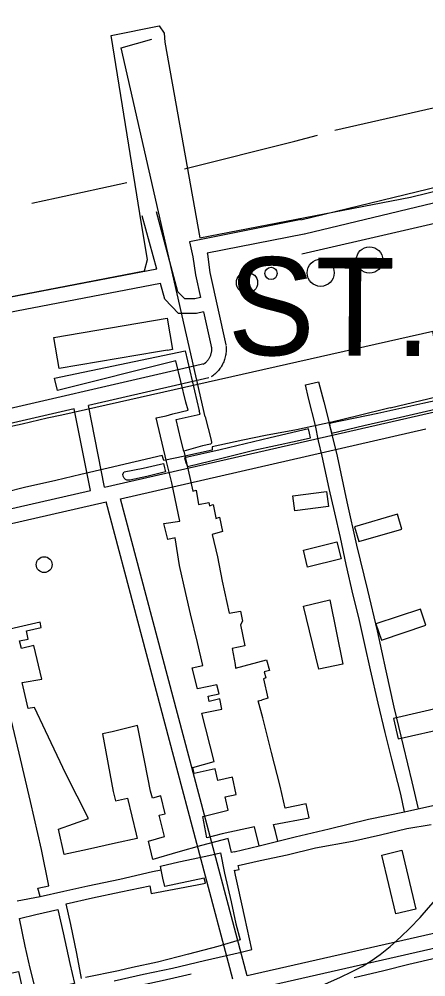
# Model space of a CAD drawing. Extents: x 3392644 to 3430565, y 576657 to 602123.
# Drawn here: x 3418875 to 3419706, y 584989 to 586945 of the extents above; entities that cross this region are included whole.
import ezdxf

# ---------------------------------------------------------------- set-up
doc = ezdxf.new("R2010")
doc.units = 0
for name, color, linetype in [('V-BLDG-OTLN', 7, 'Continuous'), ('V-DOMW-TANK', 7, 'Continuous'), ('V-RAIL-TRAK', 7, 'Continuous'), ('V-ROAD-CNTR', 7, 'Continuous'), ('V-SITE-OTLN', 7, 'Continuous'), ('V-TOPO-GNAM-IDEN', 7, 'Continuous'), ('V-TOPO-SHOR', 7, 'Continuous'), ('V-UTIL-LINE', 7, 'Continuous')]:
    doc.layers.add(name, color=color, linetype=linetype)

msp = doc.modelspace()

# ---------------------------------------------------------------- linework, layer by layer
at = {"layer": 'V-BLDG-OTLN'}
for points in [[(3419158, 586265.5), (3418957, 586231.4), (3418946.2, 586295.1), (3419178, 586334.4), (3419188.8, 586270.5), (3419178.2, 586268.7), (3419178.2, 586268.9)], [(3419434.6, 585971.9), (3419503.5, 585980.8), (3419507.5, 585949.9), (3419438.6, 585941)], [(3419648.7, 585934.1), (3419560.8, 585908.6), (3419569.6, 585878.2), (3419657.6, 585903.7)], [(3419456.2, 585860.9), (3419524.6, 585877.9), (3419533.3, 585843.1), (3419464.9, 585826.1)], [(3419456.3, 585746.5), (3419510.1, 585759.3), (3419537.1, 585628), (3419487.4, 585617.5)], [(3419695.3, 585740.6), (3419604.3, 585710.2), (3419615.5, 585676.9), (3419706.4, 585707.3)], [(3419743.5, 585540.6), (3419640.2, 585517.3), (3419649.6, 585475.6), (3419753, 585498.9)], [(3419616.5, 585238.1), (3419657.5, 585247.8), (3419686, 585127.8), (3419645.3, 585118.2)]]:
    msp.add_lwpolyline(points, close=True, dxfattribs=at)
at = {"layer": 'V-DOMW-TANK'}
for centre, radius in [((3419591.4, 586453.3), 27), ((3419491.4, 586427.2), 27.7), ((3419340.9, 586406.8), 21.6), ((3419390, 586426), 12.5), ((3418926.3, 585831.2), 16.2)]:
    msp.add_circle(centre, radius, dxfattribs=at)
at = {"layer": 'V-RAIL-TRAK'}
for points in [[(3419499.9, 584974.8), (3419531.9, 584989), (3419554.4, 584999.8), (3419576.5, 585010.3), (3419594.9, 585022.2), (3419613.3, 585035), (3419633.7, 585051.6), (3419655.4, 585071), (3419673.7, 585088.8), (3419694.5, 585110.3), (3419712.1, 585130.2), (3419726.8, 585147.1), (3419741.8, 585165.7), (3419759.4, 585186.4), (3419778.1, 585207.9), (3419792.4, 585223.6), (3419811.6, 585241.8), (3419831.6, 585257.9), (3419853.7, 585273.3), (3419878.7, 585289.5), (3419895, 585299), (3419910, 585308.2)], [(3419559.7, 584988.4), (3419620.3, 585002.7), (3419671.4, 585015.4), (3419727.6, 585028.2), (3419781.6, 585039.5), (3419818.6, 585046.2), (3419857.2, 585056.7), (3419903.9, 585067.9), (3419945.5, 585077), (3419963, 585081.5), (3419981.3, 585085.2), (3420023.6, 585095.8), (3420054.2, 585102.5), (3420089.2, 585111.2), (3420126.5, 585119.1), (3420151.3, 585124.4), (3420195.8, 585135.3), (3420227.5, 585143.2), (3420251.6, 585148.4), (3420288.4, 585157.1), (3420316.2, 585163.1), (3420340.2, 585168.7), (3420377.5, 585177), (3420381.1, 585177.8)], [(3418836.6, 584822.8), (3418864.9, 584833.7), (3418885.8, 584842.9), (3418905.1, 584853.7), (3418933.7, 584872.1), (3418945.1, 584880), (3418963.5, 584894.9), (3418979.1, 584906.5), (3418998.7, 584920.2), (3419012.6, 584928.5), (3419026.1, 584936.4), (3419042.9, 584944.3), (3419067.9, 584954.8), (3419087.6, 584961.9), (3419109.7, 584968.6), (3419133.1, 584974.5), (3419167.6, 584982.1), (3419200.4, 584989.3), (3419227, 584995.3)]]:
    msp.add_lwpolyline(points, dxfattribs=at)
at = {"layer": 'V-ROAD-CNTR'}
for points in [[(3419451.1, 586535.5), (3419925, 586650.1)], [(3419458.1, 586506.4), (3419738.9, 586574.3)], [(3419156.4, 586434.3), (3419127, 586543.6)], [(3419245.7, 586376.7), (3419234.4, 586374), (3419213.8, 586373.9), (3419199.8, 586388.5), (3419156, 586551.4)], [(3419451.7, 586535.7), (3419223.4, 586490.5), (3419230.5, 586459.5), (3419235.6, 586422.7), (3419245.7, 586376.7)], [(3419457.5, 586506.3), (3419259.5, 586467), (3419260, 586464.9), (3419265.2, 586428), (3419297.6, 586280.3)], [(3419156.4, 586434.3), (3418822, 586370.4)], [(3419164.2, 586405.3), (3418815.9, 586338.7)], [(3419252.2, 586347.4), (3419238, 586344), (3419201.1, 586343.8), (3419172.8, 586373.2), (3419164.2, 586405.3)], [(3419252.2, 586347.4), (3419268.3, 586273.9)], [(3419268, 586275.6), (3419268.2, 586273.9), (3419268.3, 586272.4), (3419268.3, 586271), (3419268.3, 586269.6), (3419268.2, 586268.1), (3419268.1, 586266.7), (3419267.9, 586265.2), (3419267.6, 586263.8), (3419267.3, 586262.4), (3419267, 586261), (3419266.6, 586259.6), (3419266.1, 586258.3), (3419265.6, 586256.9), (3419265, 586255.6), (3419264.4, 586254.3), (3419263.7, 586253), (3419263, 586251.8), (3419262.2, 586250.6), (3419261.4, 586249.4), (3419260.5, 586248.2), (3419259.6, 586247.1), (3419258.6, 586246), (3419257.6, 586245), (3419256.6, 586244), (3419255.5, 586243), (3419254.4, 586242.1), (3419253.2, 586241.2), (3419252, 586240.4), (3419251.4, 586240)], [(3419297.9, 586278.7), (3419298.1, 586276.3), (3419298.3, 586273.7), (3419298.3, 586271.1), (3419298.3, 586268.5), (3419298.1, 586265.9), (3419297.9, 586263.2), (3419297.5, 586260.6), (3419297.1, 586258.1), (3419296.5, 586255.5), (3419295.9, 586253), (3419295.1, 586250.4), (3419294.3, 586248), (3419293.3, 586245.5), (3419292.3, 586243.1), (3419291.1, 586240.7), (3419289.9, 586238.4), (3419288.6, 586236.2), (3419287.2, 586233.9), (3419285.7, 586231.8), (3419284.1, 586229.7), (3419282.4, 586227.7), (3419280.7, 586225.7), (3419278.9, 586223.8), (3419277, 586222), (3419275, 586220.2), (3419273, 586218.6), (3419270.9, 586217), (3419268.8, 586215.5), (3419267.9, 586214.9)], [(3419256.3, 586242.1), (3418204.9, 585999.8)], [(3419263, 586212.8), (3419017.1, 586156.2)], [(3419050, 585989.3), (3419017.1, 586156.2)], [(3419050, 585989.3), (3419840.8, 586170)], [(3418987.8, 586149.4), (3417630, 585836.5)], [(3419020.8, 585982.6), (3418987.8, 586149.4)], [(3419082.4, 585965.9), (3419706.4, 586108.5)], [(3417753.8, 585693), (3419020.8, 585982.6)], [(3417760.5, 585663.8), (3419053.2, 585959.2)], [(3419311.9, 584984.6), (3419053.2, 585959.2)], [(3419341.2, 584991.2), (3419082.4, 585965.9)], [(3419941.7, 585127.7), (3419341.2, 584991.2)], [(3419791.4, 585062.8), (3419279.1, 584946.4)]]:
    msp.add_lwpolyline(points, dxfattribs=at)
at = {"layer": 'V-SITE-OTLN'}
msp.add_lwpolyline([(3418830.7, 586373.5), (3419131.5, 586431.4), (3419137.7, 586454.6), (3419125.3, 586527.4), (3419063.2, 586911.5), (3419161.3, 586931.7), (3419171.3, 586916.3), (3419172.8, 586898.4), (3419244.6, 586498.5), (3419674.8, 586581.6), (3419894.5, 586635.1), (3419902.8, 586662.5), (3419897.6, 586716.1), (3419842, 586951.5), (3419807.5, 586977.5), (3419785.8, 587091.7), (3419891.9, 587110), (3419751.8, 587726), (3419367.2, 587647.7), (3419349.9, 587722.2), (3419764.5, 587802.1), (3419878.1, 587827.9), (3419791.9, 588187.7)], dxfattribs=at)
at = {"layer": 'V-TOPO-SHOR'}
msp.add_line((3419520.1, 586718.2), (3419873.4, 586799), dxfattribs=at)
for points in [[(3419213.2, 586639.3), (3419438.8, 586696.3), (3419484.7, 586708.1)], [(3418901.3, 586569.7), (3418951.8, 586580.1), (3419095, 586611.9)], [(3419868.8, 586196.8), (3419782.2, 586178), (3419700.6, 586160.2), (3419608.5, 586139.8), (3419512.4, 586119.9), (3419509.4, 586118.9), (3419511, 586110.3), (3419514.6, 586099.8)], [(3419514.6, 586099.8), (3419579.4, 586115.5), (3419654.9, 586132.2), (3419725.8, 586148.9), (3419798.2, 586164.1), (3419872, 586183.1)], [(3419470.5, 586089.9), (3419468.4, 586100), (3419466.8, 586108.2), (3419388.3, 586089.9), (3419286, 586065.4), (3419213.1, 586049.1), (3419215.7, 586040), (3419219.3, 586031.9)], [(3419219.3, 586031.9), (3419289.2, 586048.6), (3419355, 586064.8), (3419443.7, 586084.2), (3419470.5, 586089.9)], [(3419136.2, 586011.1), (3419101.3, 586003.8), (3419095.2, 586003.7), (3419092.6, 586005.2), (3419090.1, 586007.7), (3419088, 586011.8), (3419087.5, 586015.8), (3419090, 586020.4), (3419128.5, 586028.3), (3419164, 586036.6), (3419170, 586037.7), (3419172.1, 586028.6), (3419174.2, 586020.5), (3419136.2, 586011.1)]]:
    msp.add_lwpolyline(points, dxfattribs=at)
at = {"layer": 'V-UTIL-LINE'}
for points in [[(3419255.2, 586133), (3419083.7, 586886.8), (3419146.6, 586904)], [(3419633.7, 586151.1), (3420071.9, 586256), (3420378.7, 586321.6), (3420603.3, 586372.6), (3420839, 586426.1), (3421186.1, 586510.6), (3421174.4, 586569.8), (3421031.9, 586538.1), (3421022.3, 586577.5), (3420839.2, 586533.5), (3420530, 586461.1), (3420363.4, 586418.4), (3420342.4, 586414.3), (3420336.1, 586437.9), (3420071.5, 586378.6), (3420070.5, 586387.2), (3419786.8, 586321.1), (3419788.6, 586310.6), (3419766.3, 586305), (3419770.1, 586292.6), (3419725.5, 586282.1), (3419720.5, 586307.1), (3418962.6, 586136.7)], [(3419452.7, 586465.8), (3419837.5, 586554.5), (3419866.4, 586459.9)], [(3419216, 586163.1), (3419195.3, 586247.1), (3418953.9, 586186.7), (3418947.5, 586211.7), (3419214.3, 586267.7), (3419243.2, 586145.6)], [(3419480.6, 586115), (3419466.6, 586171.4), (3419460.5, 586198.5), (3419487.2, 586204.5), (3419498.1, 586163.9), (3419508.8, 586121.1)], [(3419365.9, 585257.1), (3419356, 585295.7), (3419290.5, 585281.4), (3419258.8, 585273.6), (3419250.9, 585317.1), (3419302.6, 585329.8), (3419296.2, 585356.7), (3419319, 585361.7), (3419311.1, 585397.5), (3419281.5, 585390.5), (3419275.8, 585413.9), (3419233.1, 585404.6), (3419230.2, 585417), (3419273.6, 585429.1), (3419248.8, 585527.6), (3419289.5, 585536.2), (3419285.2, 585556.9), (3419263.9, 585551.9), (3419261.7, 585562.9), (3419283.8, 585567.2), (3419279.5, 585585.8), (3419239.5, 585577.3), (3419228.9, 585620.7), (3419250.9, 585625), (3419239.6, 585671.9), (3419225.4, 585730.4), (3419216.1, 585772.5), (3419203.3, 585829.7), (3419194, 585885.6), (3419178.8, 585882.7), (3419171, 585915.1), (3419203.4, 585920.2), (3419187, 585998.1), (3419176.4, 586041.5), (3419155.1, 586131.1), (3419175.8, 586135.4), (3419189.5, 586138.9), (3419220.6, 586146.7), (3419216, 586163.1)], [(3418962.6, 586136.7), (3418932.6, 586130.2), (3418881.7, 586118), (3418847, 586110.5), (3418807.2, 586103), (3418759.3, 586091.7), (3418711.9, 586080.8), (3418657.7, 586067.7), (3418598.4, 586052.9), (3418531.5, 586037.6), (3418470, 586024), (3418432.8, 586016.1), (3418435, 586004.7), (3418415.1, 585999.9)], [(3419633.7, 586151.1), (3419567.7, 586135), (3419514.3, 586122.3), (3419442.3, 586106.6), (3419378.7, 586094.7), (3419332.5, 586085.1), (3419269.9, 586071.5), (3419269.9, 586064.7), (3419214, 586052.5), (3419170.8, 586043.7), (3419167.7, 586054.3), (3419112.7, 586041.2), (3419057.2, 586028.5), (3419001.3, 586015.4), (3418950, 586002.8), (3418886.1, 585988.8), (3418848.8, 585979.2)], [(3419211.6, 586062.7), (3419205.9, 586086.8), (3419196, 586127.5), (3419244.9, 586138.2), (3419243.2, 586145.6)], [(3419255.2, 586133), (3419267.4, 586085.6), (3419268.7, 586080.9), (3419268.3, 586079.2), (3419266.6, 586077.5), (3419249.7, 586073.6), (3419211.6, 586062.7), (3419223.8, 586009.3), (3419229.9, 585981.4), (3419236.7, 585983.1), (3419242, 585954.3), (3419262.8, 585958.3), (3419264.1, 585951.5), (3419271.7, 585953.7), (3419277, 585926.5), (3419277.4, 585925.7), (3419285, 585927.9), (3419291.1, 585898.6), (3419269.5, 585893), (3419280.9, 585846.8), (3419290.1, 585797.7), (3419304.6, 585732), (3419327.4, 585736), (3419331.8, 585715.6), (3419327.6, 585708), (3419336.4, 585665.6), (3419310.5, 585659.9), (3419316.7, 585627.3), (3419317.6, 585620.1), (3419381.1, 585636.6), (3419386.8, 585615), (3419375.8, 585612.4), (3419379.7, 585599.7), (3419374.6, 585598), (3419383.3, 585558.2), (3419370.6, 585554.7)], [(3419662.8, 585326.5), (3419655, 585362.5), (3419637.1, 585433.7), (3419623.2, 585488.3), (3419608.8, 585548.4), (3419593.5, 585616.6), (3419581.7, 585667.9), (3419569.4, 585723.4), (3419558.1, 585769.1), (3419543.7, 585831.4), (3419531.9, 585886.4), (3419520.5, 585936.9), (3419509.1, 585986.8), (3419494.7, 586052.9), (3419487.3, 586084), (3419480.6, 586115)], [(3419691.3, 585332.7), (3419678.6, 585387.4), (3419660.7, 585461.5), (3419641.6, 585539.8), (3419625.4, 585614), (3419607.4, 585696.2), (3419587.8, 585779.2), (3419565.5, 585871.1), (3419545.9, 585959.6), (3419525.7, 586052.8), (3419513.9, 586102.4), (3419508.8, 586121.1)], [(3418918, 585153.7), (3418913.7, 585170.2), (3418935.8, 585175.2), (3418920.8, 585249.7), (3418898.7, 585347.6), (3418875.3, 585446.1), (3418849.7, 585555), (3418822.7, 585665.3), (3418793.6, 585796.3), (3418771.5, 585896.3), (3418758.9, 585951.9)], [(3419314.7, 585244.9), (3419309.2, 585243.4), (3419302.1, 585271.7), (3419247.6, 585257.5), (3419199.4, 585244.1), (3419148.4, 585229.3), (3419139.9, 585266.5), (3419172.2, 585275.7), (3419161.6, 585319.8), (3419174, 585322.6), (3419164.8, 585359.2), (3419147.6, 585354.2), (3419144, 585368.7), (3419131.9, 585428), (3419116.9, 585502.4), (3419065.2, 585489.7), (3419045.9, 585485.4), (3419067.4, 585368.2), (3419072.3, 585348.9), (3419096.5, 585354.6), (3419114.2, 585280.8), (3419116.3, 585271.8), (3419072.2, 585262.6), (3419015, 585249.8), (3418967.4, 585239.1), (3418955.4, 585290.8), (3419016.7, 585312.6), (3418970.5, 585404.1), (3418929.2, 585491.5), (3418906.8, 585539.7), (3418893.7, 585537.5), (3418881.6, 585590.6), (3418921.6, 585597.1), (3418905.2, 585666), (3418880.4, 585659.7), (3418876.2, 585675.5), (3418893.4, 585679.1), (3418890.5, 585696.3), (3418920.2, 585702.7), (3418918, 585713.8), (3418856, 585699.5)], [(3419403.6, 585266.3), (3419399.4, 585286.3), (3419395.1, 585300.7), (3419468.2, 585314.3), (3419461.8, 585342.6), (3419419.1, 585334), (3419408.4, 585378.8), (3419390.7, 585447.8), (3419373, 585518.1), (3419363.8, 585553.2), (3419370.6, 585554.7)], [(3419314.7, 585244.9), (3419365.9, 585257.1), (3419403.6, 585266.3), (3419439.2, 585275), (3419508.6, 585292), (3419589.5, 585311.6), (3419662.8, 585326.5), (3419732.7, 585341.8), (3419802.6, 585357.1), (3419867, 585372), (3419947.1, 585390.3), (3420000, 585401.7), (3420063.1, 585417), (3420117.4, 585428.8), (3420172.8, 585442.3), (3420233.8, 585456.3), (3420297.4, 585471.1), (3420348.6, 585482.9), (3420407.9, 585496.5), (3420451.7, 585506.9)], [(3419322.9, 585216.5), (3419367.8, 585227), (3419422.9, 585238.8), (3419480.9, 585252.7), (3419556.8, 585266.8), (3419613.9, 585279.5), (3419667.3, 585292.2), (3419717.3, 585300.6)], [(3418871.4, 585144.9), (3418918, 585153.7), (3418966.3, 585164.2), (3419015.4, 585175.1), (3419081.1, 585189.1), (3419147.6, 585204.4), (3419165.4, 585207.9), (3419164, 585215.1), (3419201.3, 585224.3), (3419256.8, 585236.1), (3419286.5, 585242.7), (3419295.2, 585201.2), (3419308.3, 585142.3), (3419318.4, 585097.4), (3419326.7, 585064.8), (3419281.4, 585051.7), (3419221.2, 585035.6), (3419158.1, 585019.1), (3419106.9, 585008.2), (3419078.1, 585002), (3419010.7, 584988)], [(3419069.4, 584981.4), (3419129.2, 584994.9), (3419188.9, 585007.2), (3419254.1, 585022.9), (3419328.7, 585039.9), (3419351.1, 585045.2), (3419336.3, 585110.4), (3419323.1, 585172.3), (3419317.4, 585197.2), (3419315.3, 585207), (3419314.8, 585206.6), (3419324.6, 585208.7), (3419322.9, 585216.5)], [(3419002.7, 584986.3), (3418993, 585037.1), (3418980.7, 585096), (3418971.5, 585138.8), (3419024.9, 585150.6), (3419082.9, 585162.8), (3419142.2, 585175.5), (3419145.3, 585159.9), (3419239.4, 585177.5), (3419256.3, 585181), (3419253.3, 585190.7), (3419172.8, 585173.6), (3419168.9, 585191), (3419165.4, 585207.9)], [(3418910.2, 584958.8), (3418898, 585007.1), (3418887.9, 585052), (3418875.7, 585108.3), (3418909.5, 585116.6), (3418954.4, 585126.7), (3418965.4, 585079.2), (3418978.9, 585016.9), (3418988.5, 584975.9), (3418954.6, 584968.4), (3418910.2, 584958.8)], [(3418817.4, 584988.2), (3418848.7, 584994.7), (3418873.7, 585000), (3418880.7, 584969.5)]]:
    msp.add_lwpolyline(points, dxfattribs=at)

# ---------------------------------------------------------------- texts
at = {"layer": 'V-TOPO-GNAM-IDEN'}
msp.add_text('ST.', height=200, rotation=359.6858, dxfattribs=at).set_placement((3419301, 586259.4))

doc.saveas('drawing.dxf')
